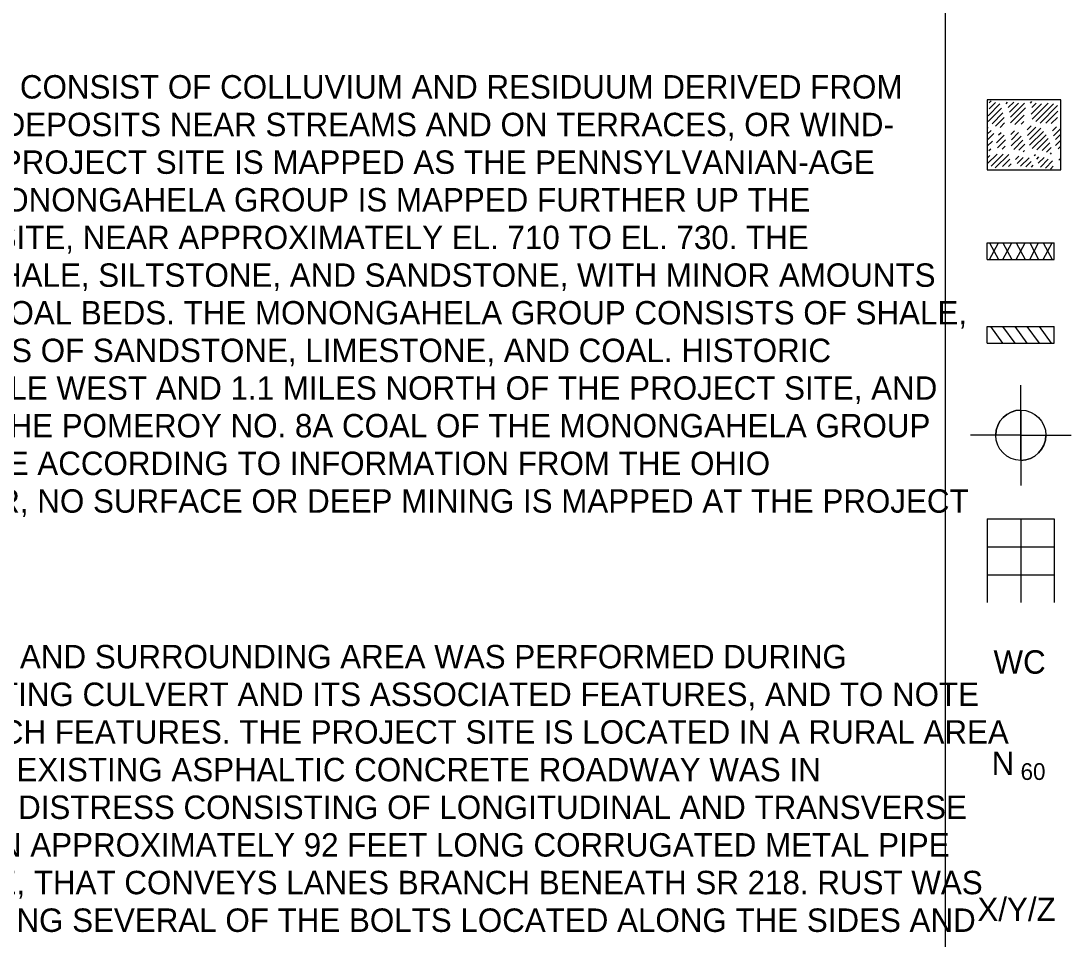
# Model space of a CAD drawing. Extents: x 0 to 34, y 0 to 22.
# Drawn here: x 6.46 to 12.74, y 10.94 to 16.43 of the extents above; entities that cross this region are included whole.
import ezdxf

# ---------------------------------------------------------------- set-up
doc = ezdxf.new("R2010")
doc.units = 0
for name, color, linetype in [('GT_Project_Soil_Boring', 7, 'Continuous'), ('GT_Project_Soil_Layers', 7, 'Continuous'), ('SH_Data', 7, 'Continuous'), ('SH_Text', 7, 'Continuous')]:
    doc.layers.add(name, color=color, linetype=linetype)

msp = doc.modelspace()

# ---------------------------------------------------------------- linework, layer by layer
at = {"layer": 'GT_Project_Soil_Boring'}
for p, q in [((12.4372, 13.9511), (12.4372, 14.2511)), ((12.4372, 14.1011), (12.4372, 13.9511)), ((12.4372, 13.9511), (12.1372, 13.9511)), ((12.4372, 13.9511), (12.2872, 13.9511)), ((12.4372, 13.9511), (12.4372, 13.6511)), ((12.4372, 13.9511), (12.7372, 13.9511)), ((12.4372, 13.8011), (12.4372, 13.9511)), ((12.4372, 13.9511), (12.5872, 13.9511)), ((12.2372, 13.4511), (12.6372, 13.4511)), ((12.2372, 13.4511), (12.2372, 12.9511)), ((12.4372, 13.4511), (12.4372, 12.9511)), ((12.6372, 13.4511), (12.6372, 12.9511)), ((12.2372, 13.2844), (12.6372, 13.2844)), ((12.2372, 13.1178), (12.6372, 13.1178))]:
    msp.add_line(p, q, dxfattribs=at)
msp.add_circle((12.4372, 13.9511), 0.15, dxfattribs=at)
for start, end in [(90, 180), (270, 360)]:
    msp.add_arc((12.4372, 13.9511), 0.15, start, end, dxfattribs=at)
at = {"layer": 'GT_Project_Soil_Layers'}
for p, q in [((12.2505, 15.1011), (12.3038, 15.0012)), ((12.2505, 15.0012), (12.3038, 15.1011)), ((12.3305, 15.0012), (12.3838, 15.1011)), ((12.3305, 15.1011), (12.3838, 15.0012)), ((12.4105, 15.1011), (12.4638, 15.0012)), ((12.4105, 15.0012), (12.4638, 15.1011)), ((12.4905, 15.1011), (12.5438, 15.0012)), ((12.4905, 15.0012), (12.5438, 15.1011)), ((12.5705, 15.1011), (12.6238, 15.0012)), ((12.5705, 15.0012), (12.6238, 15.1011)), ((12.2553, 14.6011), (12.3281, 14.5012)), ((12.3281, 14.6011), (12.4008, 14.5012)), ((12.4008, 14.6011), (12.4735, 14.5012)), ((12.4735, 14.6011), (12.5462, 14.5012)), ((12.5462, 14.6011), (12.619, 14.5012))]:
    msp.add_line(p, q, dxfattribs=at)
at = {"layer": 'SH_Data'}
for p, q in [((11.9872, 3.594), (11.9872, 21.0221)), ((12.2372, 15.0012), (12.2372, 15.1011)), ((12.2372, 15.1011), (12.6372, 15.1011)), ((12.6372, 15.0012), (12.6372, 15.1011)), ((12.2372, 15.0012), (12.6372, 15.0012)), ((12.2372, 14.5012), (12.2372, 14.6011)), ((12.2372, 14.6011), (12.6372, 14.6011)), ((12.6372, 14.5012), (12.6372, 14.6011)), ((12.2372, 14.5012), (12.6372, 14.5012))]:
    msp.add_line(p, q, dxfattribs=at)
msp.add_lwpolyline([(12.2372, 15.5371), (12.6767, 15.5371), (12.6767, 15.9556), (12.2372, 15.9556)], close=True, dxfattribs=at)
at = {"layer": 'SH_Text'}
for p, q in [((12.2372, 15.9556), (12.2372, 15.9556)), ((12.2478, 15.9013), (12.2864, 15.9399)), ((12.2484, 15.9373), (12.2599, 15.9487)), ((12.3491, 15.9318), (12.3582, 15.941)), ((12.3615, 15.9089), (12.395, 15.9424)), ((12.3689, 15.881), (12.4243, 15.9364)), ((12.4948, 15.9361), (12.504, 15.9453)), ((12.6767, 15.9556), (12.6767, 15.9556)), ((12.2424, 15.8605), (12.3129, 15.9311)), ((12.2429, 15.8257), (12.3225, 15.9053)), ((12.2654, 15.8128), (12.3307, 15.8781)), ((12.3754, 15.8521), (12.4594, 15.9361)), ((12.3766, 15.8179), (12.4654, 15.9067)), ((12.4985, 15.8691), (12.5604, 15.931)), ((12.5031, 15.909), (12.5291, 15.9351)), ((12.5055, 15.8408), (12.6005, 15.9358)), ((12.5263, 15.8263), (12.632, 15.9319)), ((12.552, 15.8166), (12.6562, 15.9207)), ((12.5875, 15.8167), (12.6582, 15.8874)), ((12.2856, 15.7976), (12.3376, 15.8497)), ((12.3133, 15.79), (12.3407, 15.8174)), ((12.4014, 15.8074), (12.4579, 15.8639)), ((12.439, 15.8096), (12.4557, 15.8263)), ((12.6195, 15.8134), (12.6555, 15.8494)), ((12.2372, 15.7846), (12.2431, 15.7905)), ((12.2372, 15.7493), (12.26, 15.7721)), ((12.2372, 15.7139), (12.277, 15.7537)), ((12.3045, 15.7459), (12.3198, 15.7612)), ((12.3779, 15.7486), (12.4001, 15.7708)), ((12.3809, 15.7162), (12.4244, 15.7597)), ((12.4754, 15.7754), (12.4998, 15.7997)), ((12.4772, 15.7417), (12.528, 15.7926)), ((12.4882, 15.7174), (12.5566, 15.7858)), ((12.49, 15.6839), (12.5733, 15.7671)), ((12.6272, 15.7705), (12.6498, 15.7931)), ((12.6318, 15.7397), (12.6767, 15.7846)), ((12.6448, 15.7174), (12.6767, 15.7493)), ((12.2372, 15.6786), (12.2673, 15.7086)), ((12.2926, 15.6986), (12.3375, 15.7435)), ((12.2988, 15.6695), (12.3466, 15.7173)), ((12.3797, 15.6797), (12.4388, 15.7387)), ((12.3946, 15.6592), (12.4502, 15.7148)), ((12.4247, 15.6539), (12.461, 15.6902)), ((12.506, 15.6645), (12.5881, 15.7466)), ((12.5336, 15.6568), (12.6011, 15.7243)), ((12.5645, 15.6523), (12.611, 15.6988)), ((12.645, 15.6822), (12.6767, 15.7139)), ((12.2372, 15.5725), (12.2956, 15.6309)), ((12.2372, 15.6078), (12.2525, 15.6232)), ((12.2463, 15.6523), (12.2573, 15.6633)), ((12.2598, 15.5597), (12.3316, 15.6316)), ((12.285, 15.5496), (12.3649, 15.6294)), ((12.3249, 15.6602), (12.3437, 15.679)), ((12.4508, 15.6447), (12.459, 15.6528)), ((12.5172, 15.6222), (12.5241, 15.6291)), ((12.5901, 15.6426), (12.6183, 15.6707)), ((12.6139, 15.631), (12.6208, 15.6379)), ((12.6611, 15.663), (12.6767, 15.6786)), ((12.3274, 15.5566), (12.3716, 15.6008)), ((12.3631, 15.557), (12.3793, 15.5732)), ((12.4056, 15.5995), (12.4248, 15.6187)), ((12.4158, 15.5743), (12.4518, 15.6103)), ((12.4363, 15.5594), (12.4865, 15.6096)), ((12.4672, 15.555), (12.4983, 15.5861)), ((12.5014, 15.5538), (12.5116, 15.564)), ((12.5321, 15.6016), (12.5454, 15.615)), ((12.5419, 15.5762), (12.5762, 15.6105)), ((12.5547, 15.5536), (12.6014, 15.6002)), ((12.584, 15.5475), (12.6265, 15.59)), ((12.6638, 15.595), (12.6767, 15.6078)), ((12.2372, 15.5371), (12.2372, 15.5371)), ((12.6139, 15.542), (12.6303, 15.5585)), ((12.6767, 15.5371), (12.6767, 15.5371))]:
    msp.add_line(p, q, dxfattribs=at)

# ---------------------------------------------------------------- texts
at = {"layer": 'SH_Data'}
for s, height, p in [('WC', 0.14, (12.2741, 12.5261)), ('N', 0.14, (12.263, 11.9211)), ('60', 0.1, (12.436, 11.8911)), ('X/Y/Z', 0.14, (12.1779, 11.0479))]:
    msp.add_text(s, height=height, dxfattribs=at).set_placement(p)
at = {"layer": 'SH_Text'}
for s, p in [('THE SURFICIAL MATERIALS WITHIN GALLIA COUNTY CONSIST OF COLLUVIUM AND RESIDUUM DERIVED FROM ', (1.6196, 15.9631)), ('THE LOCAL BEDROCK, LACUSTRINE AND ALLUVIAL DEPOSITS NEAR STREAMS AND ON TERRACES, OR WIND-', (1.6196, 15.7381)), ('BLOWN SILTS (LOESS). THE BEDROCK BELOW THE PROJECT SITE IS MAPPED AS THE PENNSYLVANIAN-AGE ', (1.6196, 15.5131)), ('CONEMAUGH GROUP. THE PENNSYLVANIAN-AGE MONONGAHELA GROUP IS MAPPED FURTHER UP THE ', (1.6196, 15.2881)), ('HILLSIDES AND RIDGELINES ABOVE THE PROJECT SITE, NEAR APPROXIMATELY EL. 710 TO EL. 730. THE ', (1.6196, 15.0631)), ('CONEMAUGH GROUP CONSISTS OF CLAYSTONE, SHALE, SILTSTONE, AND SANDSTONE, WITH MINOR AMOUNTS ', (1.6196, 14.8381)), ('OF LIMESTONE AND GENERALLY THIN ECONOMIC COAL BEDS. THE MONONGAHELA GROUP CONSISTS OF SHALE, ', (1.6196, 14.6131)), ('SILTSTONE, AND MUDSTONE, WITH MINOR AMOUNTS OF SANDSTONE, LIMESTONE, AND COAL. HISTORIC ', (1.6196, 14.3881)), ('SURFACE MINING IS LOCATED WITHIN ABOUT 0.6 MILE WEST AND 1.1 MILES NORTH OF THE PROJECT SITE, AND ', (1.6196, 14.1631)), ('AN ABANDONED MINE PORTAL ASSOCIATED WITH THE POMEROY NO. 8A COAL OF THE MONONGAHELA GROUP ', (1.6196, 13.9381)), ('IS LOCATED 1.6 MILES NORTH OF THE PROJECT SITE ACCORDING TO INFORMATION FROM THE OHIO ', (1.6196, 13.7131)), ('DEPARTMENT OF NATURAL RESOURCES. HOWEVER, NO SURFACE OR DEEP MINING IS MAPPED AT THE PROJECT ', (1.6196, 13.4881)), ('A VISUAL RECONNAISSANCE OF THE PROJECT SITE AND SURROUNDING AREA WAS PERFORMED DURING ', (1.6196, 12.5581)), ('DRILLING TO REVIEW THE CONDITION OF THE EXISTING CULVERT AND ITS ASSOCIATED FEATURES, AND TO NOTE ', (1.6196, 12.3331)), ('ANY SIGNS OF DISTRESS, SEEPAGE, OR OTHER SUCH FEATURES. THE PROJECT SITE IS LOCATED IN A RURAL AREA ', (1.6196, 12.1081)), ('WITHIN A WIDE, GENERALLY WOODED VALLEY. THE EXISTING ASPHALTIC CONCRETE ROADWAY WAS IN ', (1.6196, 11.8831)), ('MODERATE CONDITION, WITH SIGNS OF PAVEMENT DISTRESS CONSISTING OF LONGITUDINAL AND TRANSVERSE ', (1.6196, 11.6581)), ('CRACKING NOTED. THE EXISTING STRUCTURE IS AN APPROXIMATELY 92 FEET LONG CORRUGATED METAL PIPE ', (1.6196, 11.4331)), ('ARCH, WITH AN 18.5-FOOT SPAN AND 9.5-FOOT RISE, THAT CONVEYS LANES BRANCH BENEATH SR 218. RUST WAS ', (1.6196, 11.2081)), ('OBSERVED ALONG THE FLOWLINE AND SURROUNDING SEVERAL OF THE BOLTS LOCATED ALONG THE SIDES AND ', (1.6196, 10.9831))]:
    msp.add_text(s, height=0.14, dxfattribs=at).set_placement(p)

doc.saveas('drawing.dxf')
